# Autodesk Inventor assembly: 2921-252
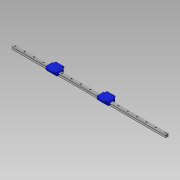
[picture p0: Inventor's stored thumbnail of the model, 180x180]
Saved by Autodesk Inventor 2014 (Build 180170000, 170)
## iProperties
Company: NHTSA/VRTC
Created: 2012-02
Part Number: 2921-252
Project: CHILD SIDE IMPACT SLED
Description: LINEAR RAIL
Document SubType Name: Assembly
Designer: Mike Vanvoorhis
Mass: 8778.73 g
Surface Area: 2235.81 cm^2
Volume: 1118.31 cm^3
Density: 7.85 g/cm^3
Title: Linear Rail
Subject: Child Side Impact Sled
Author: Dave Walker
Comments: Reference Supplier: THK - http://www.thk.com/us/index.html Linear Rail System:  HSR-30B
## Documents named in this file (3)
- B:\VRTC_DWG\BIO\Non-P572\Child Side-Frontal Impact Sled\Side Impact Sled\Rail.iam
- B:\VRTC_DWG\BIO\Non-P572\Child Side-Frontal Impact Sled\Side Impact Sled\2921-116-1.ipt
- B:\VRTC_DWG\BIO\Non-P572\Child Side-Frontal Impact Sled\Side Impact Sled\2921-116-2.ipt
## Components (3 placed, 2 different names)
1. 2921-116-1:1 — Mate:1, Mate:2, Mate:3, Mate:4
2. 2921-116-2:1 — Mate:1, Mate:2, Flush:1
3. 2921-116-2:2 — Mate:3, Mate:4, Flush:1
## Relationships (5: Mate 4, Flush 1)
- Mate:1: 2921-116-1:1 ↔ 2921-116-2:1
- Mate:2: 2921-116-1:1 ↔ 2921-116-2:1
- Mate:3: 2921-116-1:1 ↔ 2921-116-2:2
- Mate:4: 2921-116-1:1 ↔ 2921-116-2:2
- Flush:1: 2921-116-2:1 ↔ 2921-116-2:2
